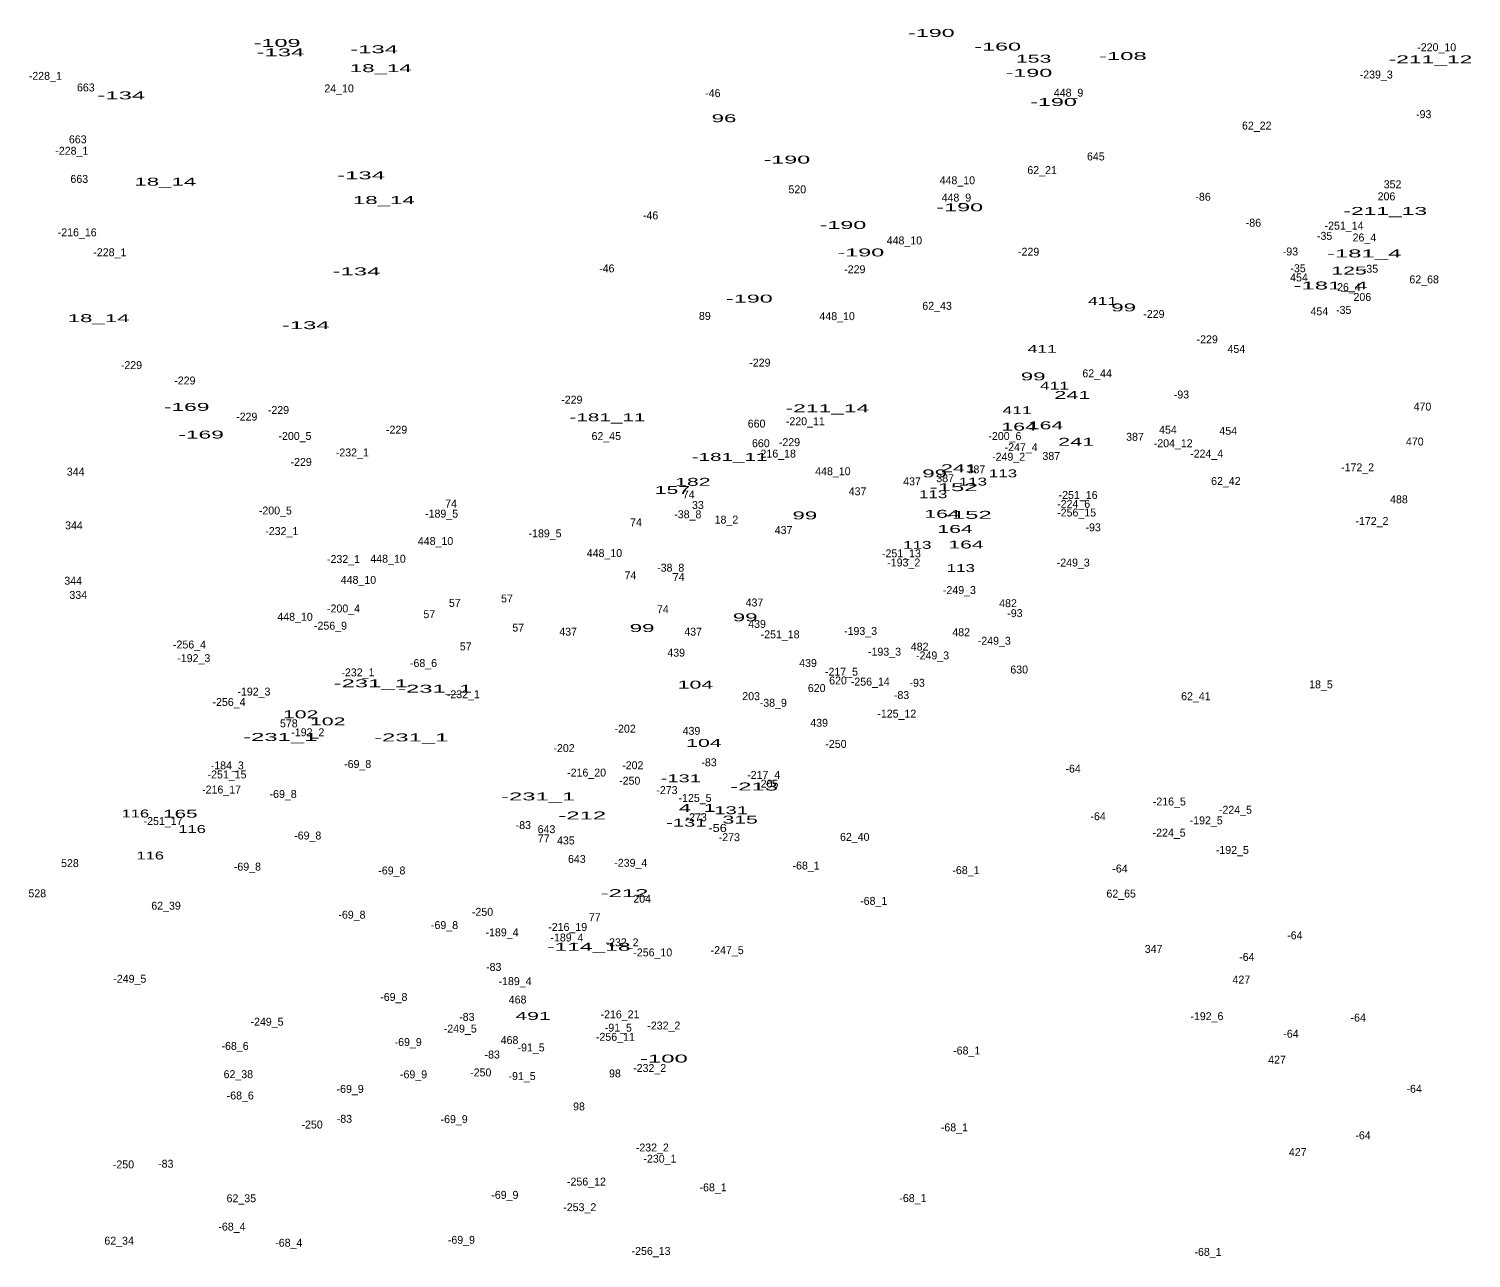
# Model space of a CAD drawing. Extents: x -661742 to -657295, y -1002932 to -996888.
# Drawn here: x -661184 to -660457, y -1002024 to -1001403 of the extents above; entities that cross this region are included whole.
import ezdxf
from ezdxf.enums import TextEntityAlignment as Align

# ---------------------------------------------------------------- set-up
doc = ezdxf.new("R2010")
doc.units = 0
doc.header["$LTSCALE"] = 1.6
doc.layers.add('24', color=7, linetype='Continuous')

msp = doc.modelspace()

# ---------------------------------------------------------------- texts
at = {"layer": '24'}
for s, width, p in [('-190', 2.2, (-660728.931, -1001407.34)), ('-109', 2.2, (-661058.981, -1001412.38)), ('-134', 2.25, (-661010.036, -1001415.57)), ('-160', 2.2, (-660695.441, -1001414.22)), ('-134', 2.25, (-661057.336, -1001417.13)), ('153', 2, (-660677.297, -1001420.32)), ('-108', 2.25, (-660632.287, -1001419.01)), ('-211_12', 2.15, (-660477.094, -1001420.67)), ('18_14', 2.1, (-661006.691, -1001425.13)), ('-190', 2.2, (-660679.691, -1001427.47)), ('-134', 2.25, (-661137.596, -1001438.85)), ('-190', 2.2, (-660667.281, -1001442.21)), ('96', 2.1, (-660833.511, -1001450.39)), ('-190', 2.2, (-660801.821, -1001471.26)), ('-134', 2.25, (-661016.626, -1001479.19)), ('18_14', 2.1, (-661115.381, -1001482.4)), ('18_14', 2.1, (-661005.141, -1001491.69)), ('-190', 2.2, (-660714.581, -1001495.34)), ('-211_13', 2.15, (-660499.904, -1001497.19)), ('-190', 2.2, (-660773.521, -1001504.27)), ('-190', 2.2, (-660764.491, -1001518.12)), ('-181_4', 2.25, (-660510.573, -1001518.62)), ('-134', 2.25, (-661018.946, -1001527.67)), ('125', 2, (-660518.157, -1001527.26)), ('-181_4', 2.25, (-660527.433, -1001534.81)), ('-190', 2.2, (-660820.711, -1001541.4)), ('411', 1.65, (-660642.499, -1001542.58)), ('99', 2.1, (-660631.891, -1001545.86)), ('18_14', 2.1, (-661149.031, -1001551.28)), ('-134', 2.25, (-661044.536, -1001554.82)), ('411', 1.65, (-660672.959, -1001566.77)), ('99', 2.1, (-660677.541, -1001580.68)), ('411', 1.65, (-660666.769, -1001585.34)), ('241', 2.05, (-660657.763, -1001590.06)), ('-169', 2.15, (-661104.609, -1001596.06)), ('-211_14', 2.15, (-660781.349, -1001596.75)), ('411', 1.65, (-660685.619, -1001597.72)), ('-181_11', 1.95, (-660892.34, -1001601.3)), ('164', 2, (-660671.288, -1001605.34)), ('-169', 2.15, (-661097.339, -1001610.02)), ('164', 2, (-660684.628, -1001606.02)), ('241', 2.05, (-660655.823, -1001613.66)), ('-181_11', 1.95, (-660830.69, -1001621.28)), ('241', 2.05, (-660714.973, -1001627.01)), ('182', 2, (-660849.237, -1001633.88)), ('99', 2.1, (-660727.241, -1001629.63)), ('113', 1.6, (-660707.954, -1001633.76)), ('113', 1.6, (-660692.774, -1001629.6)), ('157', 2, (-660859.533, -1001637.97)), ('113', 1.6, (-660727.974, -1001640.14)), ('-152', 2.25, (-660717.671, -1001636.57)), ('99', 2.1, (-660792.741, -1001650.82)), ('164', 2, (-660723.508, -1001650.01)), ('-152', 2.25, (-660710.491, -1001650.54)), ('164', 2, (-660716.928, -1001657.66)), ('113', 1.6, (-660735.994, -1001665.68)), ('164', 2, (-660711.418, -1001665.49)), ('113', 1.6, (-660714.044, -1001677.38)), ('99', 2.1, (-660874.861, -1001707.66)), ('99', 2.1, (-660822.841, -1001702.24)), ('-231_1', 2.25, (-661011.737, -1001735.56)), ('104', 2, (-660847.919, -1001736.21)), ('-231_1', 2.25, (-660979.237, -1001738.27)), ('102', 2, (-661047.124, -1001751.19)), ('102', 2, (-661033.444, -1001754.76)), ('-231_1', 2.25, (-661057.377, -1001762.64)), ('-231_1', 2.25, (-660991.287, -1001762.84)), ('104', 2, (-660843.669, -1001765.62)), ('-131', 1.9, (-660855.327, -1001783.48)), ('-213', 2.25, (-660818.321, -1001787.63)), ('-231_1', 2.25, (-660927.277, -1001792.63)), ('116', 1.55, (-661130.489, -1001801.25)), ('165', 1.95, (-661107.803, -1001801.32)), ('-212', 2.25, (-660905.041, -1001802.24)), ('4_1', 2.1, (-660846.995, -1001798.48)), ('-131', 1.9, (-660831.587, -1001799.58)), ('116', 1.55, (-661101.869, -1001809.09)), ('-131', 1.9, (-660852.517, -1001805.87)), ('-56', 1.2, (-660836.74, -1001808.55)), ('315', 2, (-660825.367, -1001804.33)), ('116', 1.55, (-661122.989, -1001822.44)), ('-212', 2.25, (-660883.711, -1001841.43)), ('-114_18', 2.15, (-660901.749, -1001868.48)), ('491', 2, (-660929.858, -1001903.4)), ('-100', 2.25, (-660863.833, -1001924.9))]:
    msp.add_text(s, height=4, dxfattribs=dict(at, width=width)).set_placement(p, align=Align.CENTER)
for s, p in [('-220_10', (-660473.933, -1001414.56)), ('-228_1', (-661175.936, -1001429.01)), ('-239_3', (-660504.468, -1001428.34)), ('663', (-661155.488, -1001434.86)), ('24_10', (-661027.717, -1001435.34)), ('-46', (-660839.145, -1001437.73)), ('448_9', (-660659.679, -1001437.49)), ('-93', (-660480.51, -1001448.33)), ('62_22', (-660564.73, -1001454.11)), ('-228_1', (-661162.556, -1001466.81)), ('663', (-661159.558, -1001461.05)), ('645', (-660645.917, -1001469.68)), ('663', (-661158.788, -1001481.02)), ('448_10', (-660715.802, -1001481.71)), ('62_21', (-660673.024, -1001476.56)), ('520', (-660796.531, -1001486.27)), ('352', (-660496.217, -1001483.73)), ('448_9', (-660716.279, -1001490.44)), ('-86', (-660591.82, -1001490.02)), ('206', (-660499.287, -1001489.8)), ('-46', (-660870.555, -1001499.4)), ('-86', (-660566.42, -1001503.11)), ('-216_16', (-661159.84, -1001507.98)), ('-35', (-660530.495, -1001509.73)), ('-251_14', (-660520.703, -1001504.6)), ('26_4', (-660510.434, -1001510.58)), ('-228_1', (-661143.366, -1001518.01)), ('448_10', (-660742.502, -1001512.06)), ('-229', (-660679.83, -1001517.75)), ('-93', (-660547.77, -1001517.63)), ('-46', (-660892.655, -1001526.17)), ('-229', (-660767.53, -1001526.59)), ('454', (-660543.436, -1001530.74)), ('-35', (-660543.915, -1001526.11)), ('-35', (-660507.375, -1001526.36)), ('62_68', (-660480.286, -1001531.69)), ('26_4', (-660518.274, -1001535.63)), ('62_43', (-660726.024, -1001545.05)), ('-35', (-660520.855, -1001547.11)), ('206', (-660511.467, -1001540.59)), ('89', (-660843.183, -1001550.15)), ('448_10', (-660776.422, -1001550.27)), ('-229', (-660616.63, -1001549.17)), ('454', (-660533.166, -1001547.81)), ('-229', (-660589.72, -1001561.97)), ('454', (-660575.036, -1001566.82)), ('-229', (-661132.47, -1001574.98)), ('-229', (-660815.42, -1001573.72)), ('-229', (-661105.52, -1001582.74)), ('62_44', (-660645.279, -1001579.12)), ('-93', (-660602.74, -1001589.8)), ('-229', (-661058.29, -1001597.64)), ('-229', (-660910.3, -1001592.43)), ('470', (-660481.141, -1001595.89)), ('-229', (-661074.31, -1001600.97)), ('660', (-660817.072, -1001604.5)), ('-220_11', (-660792.493, -1001603.33)), ('-200_5', (-661049.98, -1001610.73)), ('-229', (-660998.7, -1001607.56)), ('62_45', (-660892.904, -1001610.79)), ('-200_6', (-660691.806, -1001610.76)), ('387', (-660626.163, -1001611.15)), ('454', (-660609.546, -1001607.54)), ('454', (-660579.106, -1001608.12)), ('-232_1', (-661021.036, -1001619.05)), ('660', (-660814.942, -1001614.39)), ('-216_18', (-660807.055, -1001619.62)), ('-229', (-660800.49, -1001613.86)), ('-247_4', (-660683.616, -1001616.37)), ('-204_12', (-660606.883, -1001614.4)), ('-224_4', (-660590.011, -1001619.64)), ('470', (-660485.011, -1001613.53)), ('-229', (-661046.85, -1001623.83)), ('387', (-660706.183, -1001627.59)), ('-249_2', (-660689.932, -1001621.21)), ('387', (-660668.393, -1001620.82)), ('-172_2', (-660513.882, -1001626.57)), ('344', (-661160.616, -1001628.74)), ('448_10', (-660778.562, -1001628.52)), ('437', (-660738.667, -1001633.62)), ('387', (-660721.943, -1001632.04)), ('62_42', (-660580.324, -1001633.47)), ('74', (-660851.317, -1001640.25)), ('437', (-660766.137, -1001638.65)), ('-251_16', (-660654.875, -1001640.5)), ('-200_5', (-661059.87, -1001648.35)), ('74', (-660971.217, -1001644.83)), ('33', (-660846.677, -1001645.57)), ('-224_6', (-660657.112, -1001644.98)), ('-256_15', (-660655.621, -1001649.36)), ('488', (-660493.011, -1001642.7)), ('344', (-661161.486, -1001655.83)), ('-189_5', (-660976.002, -1001649.93)), ('74', (-660877.907, -1001654.28)), ('-38_8', (-660851.782, -1001650.25)), ('18_2', (-660832.299, -1001652.92)), ('-93', (-660647.28, -1001656.83)), ('-172_2', (-660506.612, -1001653.62)), ('-232_1', (-661056.626, -1001658.72)), ('448_10', (-660979.042, -1001663.76)), ('-189_5', (-660923.792, -1001659.87)), ('437', (-660803.457, -1001658.19)), ('448_10', (-660893.832, -1001669.83)), ('-251_13', (-660744.009, -1001669.98)), ('-232_1', (-661025.486, -1001672.84)), ('448_10', (-661003.022, -1001672.68)), ('-38_8', (-660860.412, -1001677.21)), ('-193_2', (-660742.832, -1001674.56)), ('-249_3', (-660657.312, -1001674.61)), ('344', (-661161.876, -1001683.78)), ('448_10', (-661017.952, -1001683.35)), ('74', (-660880.717, -1001681.05)), ('74', (-660856.347, -1001681.83)), ('334', (-661159.301, -1001690.93)), ('57', (-660943.033, -1001692.73)), ('-249_3', (-660714.752, -1001688.49)), ('-200_4', (-661025.474, -1001697.77)), ('57', (-660969.333, -1001694.96)), ('74', (-660864.367, -1001698.17)), ('437', (-660818.157, -1001694.76)), ('482', (-660690.221, -1001695.11)), ('-93', (-660686.73, -1001700.14)), ('448_10', (-661049.932, -1001701.97)), ('-256_9', (-661032.053, -1001706.47)), ('57', (-660982.193, -1001700.66)), ('57', (-660937.323, -1001707.44)), ('439', (-660816.847, -1001705.56)), ('437', (-660912.147, -1001709.46)), ('437', (-660849.097, -1001709.46)), ('-251_18', (-660805.209, -1001710.85)), ('-193_3', (-660764.622, -1001709.14)), ('482', (-660713.871, -1001709.76)), ('-249_3', (-660697.152, -1001714.07)), ('-256_4', (-661103.172, -1001715.96)), ('57', (-660963.823, -1001716.92)), ('439', (-660857.657, -1001720.07)), ('-193_3', (-660752.532, -1001719.59)), ('482', (-660734.811, -1001717.03)), ('-249_3', (-660728.292, -1001721.47)), ('-192_3', (-661101.012, -1001722.84)), ('-68_6', (-660985.123, -1001725.34)), ('439', (-660791.127, -1001725.29)), ('630', (-660684.597, -1001728.6)), ('-232_1', (-661018.216, -1001730.03)), ('-217_5', (-660774.262, -1001729.69)), ('620', (-660775.987, -1001734.11)), ('-256_14', (-660759.715, -1001734.69)), ('-93', (-660736.07, -1001735.28)), ('18_5', (-660532.349, -1001736.07)), ('-192_3', (-661070.672, -1001739.71)), ('-232_1', (-660965.036, -1001741.06)), ('203', (-660819.831, -1001742.03)), ('620', (-660786.747, -1001737.94)), ('-83', (-660743.945, -1001741.48)), ('62_41', (-660595.448, -1001742.05)), ('-256_4', (-661083.252, -1001744.98)), ('-38_9', (-660808.638, -1001745.37)), ('-125_12', (-660746.349, -1001750.83)), ('578', (-661053.063, -1001755.75)), ('-202', (-660883.409, -1001758.46)), ('439', (-660785.517, -1001755.47)), ('-192_2', (-661043.502, -1001760.24)), ('439', (-660849.917, -1001759.53)), ('-202', (-660914.239, -1001768.25)), ('-250', (-660777.039, -1001766.12)), ('-184_3', (-661084.15, -1001776.96)), ('-69_8', (-661018.333, -1001776.28)), ('-216_20', (-660902.845, -1001780.59)), ('-202', (-660879.529, -1001776.88)), ('-83', (-660841.075, -1001775.42)), ('-64', (-660657.385, -1001778.59)), ('-251_15', (-661084.249, -1001781.53)), ('-250', (-660881.089, -1001784.69)), ('-217_4', (-660813.506, -1001781.77)), ('205', (-660810.561, -1001786.18)), ('-216_17', (-661087.01, -1001789.15)), ('-69_8', (-661055.943, -1001791.41)), ('-273', (-660862.301, -1001789.43)), ('-125_5', (-660848.126, -1001793.38)), ('-216_5', (-660608.852, -1001795.19)), ('-224_5', (-660575.497, -1001799.36)), ('-251_17', (-661116.515, -1001805.05)), ('-83', (-660934.765, -1001807.09)), ('643', (-660923.087, -1001809.16)), ('-273', (-660847.561, -1001803.1)), ('-64', (-660644.785, -1001802.63)), ('-192_5', (-660590.242, -1001804.7)), ('-69_8', (-661043.533, -1001812.35)), ('77', (-660924.459, -1001813.74)), ('435', (-660913.301, -1001814.84)), ('-273', (-660830.821, -1001813.19)), ('62_40', (-660767.558, -1001813.04)), ('-224_5', (-660608.937, -1001810.9)), ('643', (-660907.767, -1001824.2)), ('-192_5', (-660577.062, -1001819.63)), ('528', (-661163.507, -1001826.29)), ('-69_8', (-661073.973, -1001828.06)), ('-69_8', (-661001.093, -1001830.01)), ('-239_4', (-660880.542, -1001826.12)), ('-68_1', (-660792.112, -1001827.5)), ('-68_1', (-660711.462, -1001829.83)), ('-64', (-660633.735, -1001829.01)), ('528', (-661179.987, -1001841.51)), ('204', (-660874.805, -1001844.24)), ('-68_1', (-660757.992, -1001845.34)), ('62_65', (-660633.136, -1001841.66)), ('62_39', (-661115.026, -1001847.76)), ('-69_8', (-661021.233, -1001852.31)), ('-250', (-660955.349, -1001850.86)), ('-69_8', (-660974.513, -1001857.55)), ('-216_19', (-660912.39, -1001858.49)), ('77', (-660898.739, -1001853.59)), ('-189_4', (-660945.516, -1001861.21)), ('-189_4', (-660912.756, -1001863.82)), ('-232_2', (-660884.962, -1001866.25)), ('-64', (-660545.525, -1001862.73)), ('-256_10', (-660869.445, -1001871.34)), ('-247_5', (-660831.922, -1001870.2)), ('347', (-660616.767, -1001869.56)), ('-64', (-660569.755, -1001873.62)), ('-83', (-660949.695, -1001878.66)), ('-249_5', (-661133.302, -1001884.63)), ('-189_4', (-660938.926, -1001885.84)), ('427', (-660572.497, -1001885.04)), ('-69_8', (-661000.103, -1001893.81)), ('468', (-660937.637, -1001895.12)), ('-83', (-660963.265, -1001903.87)), ('-216_21', (-660885.995, -1001902.59)), ('-192_6', (-660589.887, -1001903.52)), ('-64', (-660513.535, -1001904.23)), ('-249_5', (-661064.072, -1001906.3)), ('-249_5', (-660966.592, -1001909.78)), ('-91_5', (-660886.832, -1001909.31)), ('-232_2', (-660863.882, -1001908.23)), ('-68_6', (-661080.203, -1001918.52)), ('-69_9', (-660992.858, -1001916.57)), ('468', (-660941.717, -1001915.58)), ('-256_11', (-660888.315, -1001913.94)), ('-64', (-660547.465, -1001912.38)), ('-83', (-660950.475, -1001922.88)), ('-91_5', (-660930.842, -1001919.29)), ('-68_1', (-660711.072, -1001920.85)), ('427', (-660554.517, -1001925.48)), ('62_38', (-661078.54, -1001932.79)), ('-69_9', (-660990.138, -1001932.87)), ('-250', (-660956.239, -1001931.89)), ('98', (-660888.543, -1001932.39)), ('-232_2', (-660871.032, -1001929.68)), ('-69_9', (-661022.128, -1001940.23)), ('-91_5', (-660935.392, -1001933.74)), ('-64', (-660485.325, -1001940.16)), ('-68_6', (-661077.583, -1001943.54)), ('98', (-660906.673, -1001949.07)), ('-250', (-661041.339, -1001958.2)), ('-83', (-661025.015, -1001955.3)), ('-69_9', (-660969.668, -1001955.48)), ('-68_1', (-660717.272, -1001959.63)), ('-64', (-660511.115, -1001963.63)), ('-232_2', (-660869.682, -1001969.79)), ('-230_1', (-660865.84, -1001975.43)), ('427', (-660544.067, -1001972.11)), ('-250', (-661136.489, -1001978.32)), ('-83', (-661115.165, -1001977.99)), ('-256_12', (-660902.911, -1001986.98)), ('-68_1', (-660839.022, -1001989.89)), ('62_35', (-661077.03, -1001995.41)), ('-69_9', (-660944.078, -1001993.68)), ('-68_1', (-660738.212, -1001995.32)), ('-253_2', (-660906.282, -1001999.91)), ('-68_4', (-661081.772, -1002009.71)), ('62_34', (-661138.684, -1002016.79)), ('-68_4', (-661053.082, -1002017.85)), ('-69_9', (-660965.988, -1002016.37)), ('-256_13', (-660870.321, -1002021.99)), ('-68_1', (-660589.322, -1002022.47))]:
    msp.add_text(s, height=4, dxfattribs=at).set_placement(p, align=Align.CENTER)

doc.saveas('drawing.dxf')
